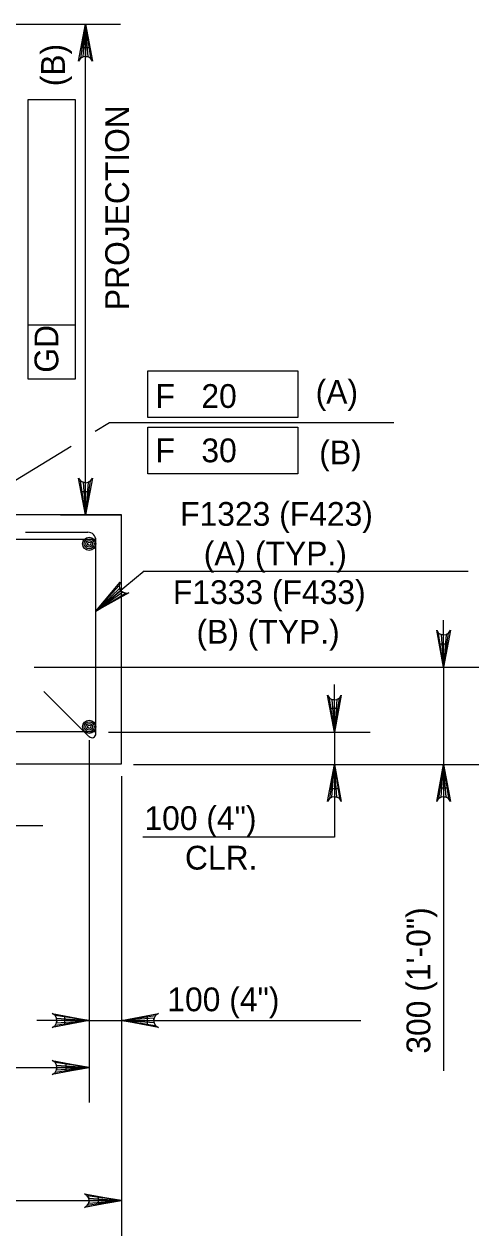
# Model space of a CAD drawing. Extents: x 638340 to 640241, y 295465 to 298435.
# Drawn here: x 640029.9 to 640087.2, y 298129.2 to 298282.1 of the extents above; entities that cross this region are included whole.
import ezdxf

# ---------------------------------------------------------------- set-up
doc = ezdxf.new("R2010")
doc.units = 0
for name, color, linetype in [('3', 7, 'Continuous'), ('4', 7, 'Continuous'), ('5', 7, 'Continuous'), ('6', 7, 'Continuous'), ('8', 7, 'Continuous'), ('9', 7, 'Continuous')]:
    doc.layers.add(name, color=color, linetype=linetype)

msp = doc.modelspace()

# ---------------------------------------------------------------- linework, layer by layer
at = {"layer": '3'}
for p, q in [((640082.78, 298203.94), (640082.78, 298206.9)), ((640031.14, 298200.99), (640087.21, 298200.99)), ((640082.78, 298200.99), (640082.78, 298188.69)), ((640069.01, 298195.79), (640069.01, 298198.79)), ((640040.5, 298192.79), (640073.51, 298192.79)), ((640069.01, 298192.79), (640069.01, 298188.69)), ((640043.69, 298188.69), (640087.21, 298188.69)), ((640043.72, 298188.69), (640073.51, 298188.69)), ((640069.01, 298185.69), (640069.01, 298179.52)), ((640082.78, 298185.74), (640082.78, 298150.02)), ((640069.01, 298179.52), (640044.84, 298179.52))]:
    msp.add_line(p, q, dxfattribs=at)
for points in [[(640082.78, 298200.99), (640081.91, 298205.65), (640082.15, 298205.29), (640082.47, 298205.11), (640082.78, 298205.05), (640083.09, 298205.11), (640083.4, 298205.29), (640083.65, 298205.65), (640082.78, 298200.99), (640083.4, 298205.29), (640083.09, 298205.11), (640082.78, 298200.99), (640082.78, 298205.05), (640082.47, 298205.11), (640082.78, 298200.99), (640082.15, 298205.29)], [(640069.01, 298192.79), (640068.13, 298197.45), (640068.38, 298197.09), (640068.69, 298196.91), (640069.01, 298196.85), (640069.32, 298196.91), (640069.63, 298197.09), (640069.88, 298197.45), (640069.01, 298192.79), (640069.63, 298197.09), (640069.32, 298196.91), (640069.01, 298192.79), (640069.01, 298196.85), (640068.69, 298196.91), (640069.01, 298192.79), (640068.38, 298197.09)], [(640069.01, 298188.69), (640069.88, 298184.03), (640069.63, 298184.39), (640069.32, 298184.58), (640069.01, 298184.63), (640068.69, 298184.58), (640068.38, 298184.39), (640068.13, 298184.03), (640069.01, 298188.69), (640068.38, 298184.39), (640068.69, 298184.58), (640069.01, 298188.69), (640069.01, 298184.63), (640069.32, 298184.58), (640069.01, 298188.69), (640069.63, 298184.39)], [(640082.78, 298188.69), (640083.65, 298184.03), (640083.4, 298184.39), (640083.09, 298184.58), (640082.78, 298184.63), (640082.47, 298184.58), (640082.15, 298184.39), (640081.91, 298184.03), (640082.78, 298188.69), (640082.15, 298184.39), (640082.47, 298184.58), (640082.78, 298188.69), (640082.78, 298184.63), (640083.09, 298184.58), (640082.78, 298188.69), (640083.4, 298184.39)]]:
    msp.add_lwpolyline(points, dxfattribs=at)
for points in [[(640082.29, 298203.94), (640083.27, 298203.94), (640082.78, 298200.99)], [(640068.51, 298195.79), (640069.51, 298195.79), (640069.01, 298192.79)], [(640068.51, 298185.69), (640069.51, 298185.69), (640069.01, 298188.69)], [(640082.29, 298185.74), (640083.27, 298185.74), (640082.78, 298188.69)]]:
    msp.add_lwpolyline(points, close=True, dxfattribs=at)
at = {"layer": '4'}
for p, q in [((639993.24, 298282.12), (640042.05, 298282.12)), ((640037.62, 298220.19), (640037.62, 298282.12)), ((640030.41, 298237.31), (640030.41, 298272.61)), ((640030.41, 298272.61), (640036.32, 298272.61)), ((640036.32, 298272.61), (640036.32, 298237.31)), ((640036.32, 298244.16), (640030.41, 298244.16)), ((640036.32, 298237.31), (640030.41, 298237.31)), ((640045.47, 298238.38), (640064.41, 298238.38)), ((640045.47, 298232.47), (640045.47, 298238.38)), ((640064.41, 298238.38), (640064.41, 298232.47)), ((640064.41, 298232.47), (640045.47, 298232.47)), ((640038.86, 298230.75), (640040.66, 298231.85)), ((640040.66, 298231.85), (640076.52, 298231.85)), ((640045.47, 298231.26), (640064.41, 298231.26)), ((640045.47, 298225.36), (640045.47, 298231.26)), ((640064.41, 298231.26), (640064.41, 298225.36)), ((640016.6, 298217.11), (640035.8, 298228.88)), ((640016.6, 298217.11), (640035.8, 298228.88)), ((640064.41, 298225.36), (640045.47, 298225.36)), ((640034.45, 298220.19), (640042.05, 298220.19)), ((640034.45, 298220.19), (640042.05, 298220.19)), ((640045.02, 298213.08), (640038.94, 298208.06)), ((640045.02, 298213.08), (640085.88, 298213.08)), ((640038.09, 298191.79), (640038.09, 298146.03)), ((640042.15, 298187.24), (640042.15, 298129.23)), ((640042.15, 298166.93), (640042.15, 298155.44)), ((640038.09, 298156.39), (640031.5, 298156.39)), ((640038.09, 298156.39), (640072.34, 298156.39)), ((639931.94, 298150.46), (640038.09, 298150.46)), ((639927.87, 298133.66), (640042.15, 298133.66))]:
    msp.add_line(p, q, dxfattribs=at)
for points in [[(640037.62, 298282.12), (640038.5, 298277.46), (640038.25, 298277.82), (640037.94, 298278), (640037.62, 298278.06), (640037.31, 298278), (640037, 298277.82), (640036.75, 298277.46), (640037.62, 298282.12), (640037, 298277.82), (640037.31, 298278), (640037.62, 298282.12), (640037.62, 298278.06), (640037.94, 298278), (640037.62, 298282.12), (640038.25, 298277.82)], [(640037.62, 298220.19), (640036.75, 298224.85), (640037, 298224.49), (640037.31, 298224.31), (640037.62, 298224.25), (640037.94, 298224.31), (640038.25, 298224.49), (640038.5, 298224.85), (640037.62, 298220.19), (640038.25, 298224.49), (640037.94, 298224.31), (640037.62, 298220.19), (640037.62, 298224.25), (640037.31, 298224.31), (640037.62, 298220.19), (640037, 298224.49)], [(640038.94, 298208.06), (640041.98, 298211.7), (640041.86, 298211.28), (640041.91, 298210.92), (640042.07, 298210.65), (640042.31, 298210.44), (640042.65, 298210.32), (640043.09, 298210.35), (640038.94, 298208.06), (640042.65, 298210.32), (640042.31, 298210.44), (640038.94, 298208.06), (640042.07, 298210.65), (640041.91, 298210.92), (640038.94, 298208.06), (640041.86, 298211.28)], [(640038.09, 298156.39), (640033.43, 298155.52), (640033.79, 298155.77), (640033.97, 298156.08), (640034.02, 298156.39), (640033.97, 298156.7), (640033.79, 298157.02), (640033.43, 298157.26), (640038.09, 298156.39), (640033.79, 298157.02), (640033.97, 298156.7), (640038.09, 298156.39), (640034.02, 298156.39), (640033.97, 298156.08), (640038.09, 298156.39), (640033.79, 298155.77)], [(640042.15, 298156.39), (640046.81, 298157.26), (640046.45, 298157.02), (640046.27, 298156.7), (640046.21, 298156.39), (640046.27, 298156.08), (640046.45, 298155.77), (640046.81, 298155.52), (640042.15, 298156.39), (640046.45, 298155.77), (640046.27, 298156.08), (640042.15, 298156.39), (640046.21, 298156.39), (640046.27, 298156.7), (640042.15, 298156.39), (640046.45, 298157.02)], [(640038.09, 298150.46), (640033.43, 298149.59), (640033.79, 298149.83), (640033.97, 298150.15), (640034.02, 298150.46), (640033.97, 298150.77), (640033.79, 298151.08), (640033.43, 298151.33), (640038.09, 298150.46), (640033.79, 298151.08), (640033.97, 298150.77), (640038.09, 298150.46), (640034.02, 298150.46), (640033.97, 298150.15), (640038.09, 298150.46), (640033.79, 298149.83)], [(640042.15, 298133.66), (640037.49, 298132.78), (640037.85, 298133.03), (640038.04, 298133.34), (640038.09, 298133.66), (640038.04, 298133.97), (640037.85, 298134.28), (640037.49, 298134.53), (640042.15, 298133.66), (640037.85, 298134.28), (640038.04, 298133.97), (640042.15, 298133.66), (640038.09, 298133.66), (640038.04, 298133.34), (640042.15, 298133.66), (640037.85, 298133.03)]]:
    msp.add_lwpolyline(points, dxfattribs=at)
for points in [[(640037.13, 298279.17), (640038.11, 298279.17), (640037.62, 298282.12)], [(640037.13, 298223.14), (640038.11, 298223.14), (640037.62, 298220.19)], [(640035, 298155.9), (640035, 298156.89), (640037.95, 298156.39)], [(640045.38, 298156.89), (640045.38, 298155.9), (640042.43, 298156.39)], [(640035.14, 298150.95), (640035.14, 298149.97), (640038.09, 298150.46)], [(640039.2, 298134.15), (640039.2, 298133.16), (640042.15, 298133.66)]]:
    msp.add_lwpolyline(points, close=True, dxfattribs=at)
at = {"layer": '5'}
for p, q in [((640038.16, 298220.18), (640038.16, 298220.18)), ((640041.92, 298220.18), (640041.92, 298220.18))]:
    msp.add_line(p, q, dxfattribs=at)
at = {"layer": '6'}
for p, q in [((640038.93, 298217.11), (639931.1, 298217.11)), ((640030.06, 298218.01), (640037.91, 298218.01)), ((640038.94, 298192.59), (640038.94, 298216.98)), ((640032.36, 298197.93), (640038.06, 298192.23)), ((639931.09, 298192.88), (640038.94, 298192.88))]:
    msp.add_line(p, q, dxfattribs=at)
for centre, radius in [((640038.09, 298216.55), 0.833), ((640038.09, 298216.55), 0.625), ((640038.09, 298216.55), 0.417), ((640038.09, 298216.55), 0.208), ((640038.09, 298193.46), 0.833), ((640038.09, 298193.46), 0.625), ((640038.09, 298193.46), 0.417), ((640038.09, 298193.46), 0.208)]:
    msp.add_circle(centre, radius, dxfattribs=at)
for centre, radius, start, end in [((640037.91, 298216.98), 1.03, 0, 90), ((640038.43, 298192.59), 0.512, 225, 0)]:
    msp.add_arc(centre, radius, start, end, dxfattribs=at)
at = {"layer": '8'}
msp.add_line((640032.23, 298180.96), (640026.09, 298180.96), dxfattribs=at)
at = {"layer": '9'}
for p, q in [((640042.15, 298220.19), (639988.51, 298220.19)), ((640042.15, 298220.19), (639988.51, 298220.19)), ((640042.15, 298188.78), (640042.15, 298220.19)), ((639927.87, 298188.78), (640042.15, 298188.78))]:
    msp.add_line(p, q, dxfattribs=at)

# ---------------------------------------------------------------- texts
at = {"layer": '3'}
for s, p in [('100 (4")', (640045.05, 298180.43)), ('CLR.', (640050.16, 298175.44)), ('100 (4")', (640047.94, 298157.56))]:
    msp.add_text(s, height=3, dxfattribs=at).set_placement(p)
msp.add_text('300 (1\'-0")', height=3.0001, rotation=90, dxfattribs=at).set_placement((640081.1, 298152.21))
at = {"layer": '4'}
for s, p in [('(B)', (640035.02, 298274.29)), ('PROJECTION', (640043.11, 298246.04)), ('GD', (640034.19, 298238.14))]:
    msp.add_text(s, height=3, rotation=90, dxfattribs=at).set_placement(p)
for s, height, p in [('(A)', 3, (640066.64, 298234.23)), ('F   20', 3, (640046.44, 298233.7)), ('F   30', 3, (640046.44, 298226.84)), ('(B)', 3, (640067.09, 298226.58)), ('F1323 (F423)', 3.0001, (640049.55, 298218.82)), ('(A) (TYP.)', 3, (640052.53, 298213.82)), ('F1333 (F433)', 3.0001, (640048.64, 298208.95)), ('(B) (TYP.)', 3, (640051.62, 298203.95))]:
    msp.add_text(s, height=height, dxfattribs=at).set_placement(p)

doc.saveas('drawing.dxf')
